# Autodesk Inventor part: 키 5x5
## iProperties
Company: 한국ATC센터
Created: 2014-10
Part Number: 키 5x5
Document SubType Name: Modeling
Designer: KYOUNG IL JANG
Density: 1 g/cm^3
Mass: 0.323175 g
Surface Area: 2.9781 cm^2
Volume: 0.323175 cm^3
Author: KYOUNG IL JANG
Revision Number: 1
